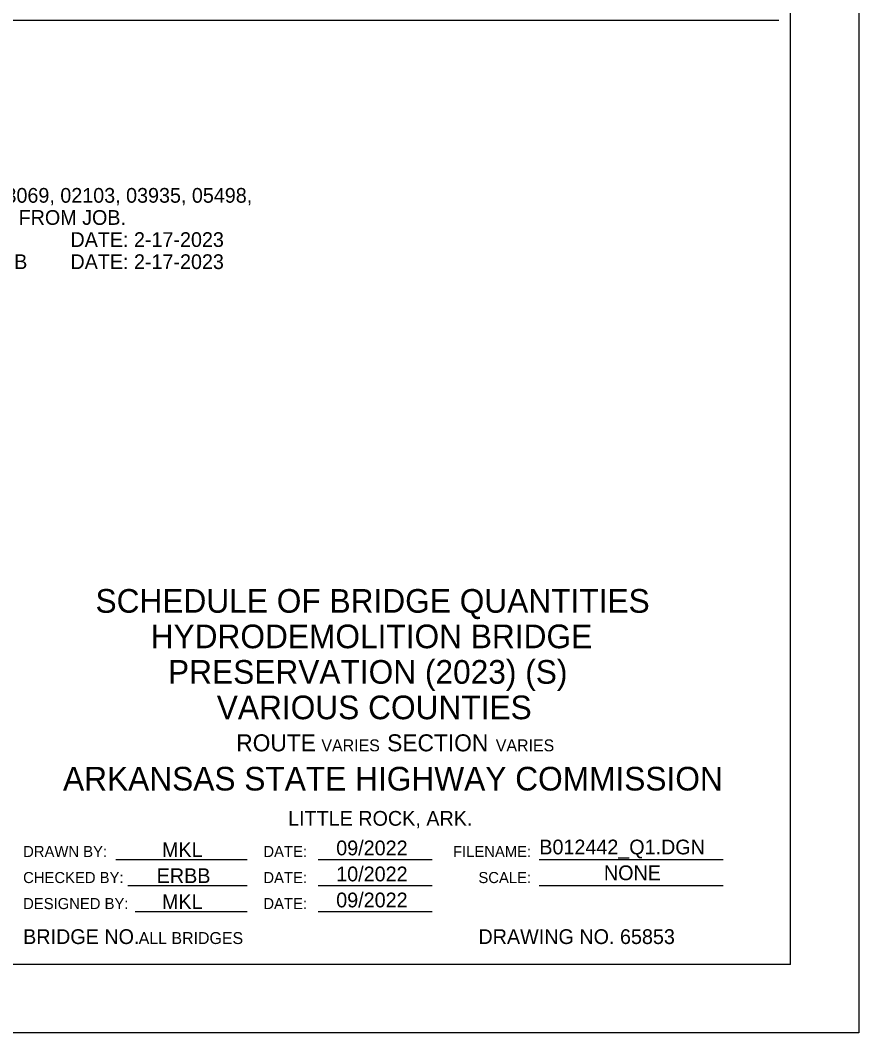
# Model space of a CAD drawing. Extents: x 18 to 14744716, y -5 to 1829144.
# Drawn here: x 44.68 to 51.78, y -5.37 to 3.2 of the extents above; entities that cross this region are included whole.
import ezdxf

# ---------------------------------------------------------------- set-up
doc = ezdxf.new("R2010")
doc.units = 0
for name, color, linetype in [('B_Copy In', 7, 'Continuous'), ('B_Text', 7, 'Continuous'), ('R_Border', 7, 'Continuous'), ('R_No Plot', 7, 'Continuous')]:
    doc.layers.add(name, color=color, linetype=linetype)

msp = doc.modelspace()

# ---------------------------------------------------------------- linework, layer by layer
at = {"layer": 'B_Text'}
for p, q in [((19.3916, 3.2008), (51.1014, 3.2008)), ((45.4897, -3.9052), (46.6013, -3.9052)), ((47.2016, -3.9052), (48.1658, -3.9052)), ((49.0717, -3.9042), (50.6292, -3.9042)), ((45.5911, -4.1255), (46.6013, -4.1255)), ((47.2016, -4.1255), (48.1658, -4.1255)), ((49.0717, -4.1245), (50.6292, -4.1245)), ((45.6521, -4.3459), (46.6013, -4.3459)), ((47.2016, -4.3459), (48.1658, -4.3459))]:
    msp.add_line(p, q, dxfattribs=at)
at = {"layer": 'R_Border'}
for q in [(51.2001, 16.0508), (19.2929, -4.7956)]:
    msp.add_line((51.2001, -4.7956), q, dxfattribs=at)
at = {"layer": 'R_No Plot'}
msp.add_lwpolyline([(17.7769, 16.6276), (51.7769, 16.6276), (51.7769, -5.3724), (17.7769, -5.3724)], close=True, dxfattribs=at)

# ---------------------------------------------------------------- texts
at = {"layer": 'B_Copy In'}
for s, height, p in [('SCHEDULE OF BRIDGE QUANTITIES', 0.2004, (45.3175, -1.8159)), ('HYDRODEMOLITION BRIDGE', 0.2004, (45.7841, -2.1165)), ('PRESERVATION (2023) (S)', 0.2004, (45.9312, -2.4171)), ('VARIOUS COUNTIES', 0.2004, (46.3438, -2.7177)), ('ROUTE    ', 0.144, (46.5087, -2.9895)), ('VARIES', 0.1008, (47.2293, -2.9895)), ('SECTION   ', 0.144, (47.7858, -2.9895)), ('VARIES', 0.1008, (48.7052, -2.9895)), ('MKL', 0.125, (45.8799, -3.8847)), ('09/2022', 0.125, (47.3545, -3.87)), ('B012442_Q1.DGN', 0.1248, (49.0738, -3.862)), ('ERBB', 0.125, (45.8352, -4.1051)), ('10/2022', 0.125, (47.3545, -4.0904)), ('NONE', 0.125, (49.6201, -4.0807)), ('MKL', 0.125, (45.8799, -4.3254)), ('09/2022', 0.125, (47.3545, -4.3107)), ('BRIDGE NO.      ', 0.125, (44.7048, -4.6211)), ('ALL BRIDGES', 0.1008, (45.6828, -4.6211)), ('DRAWING NO. 65853', 0.125, (48.5581, -4.6211))]:
    msp.add_text(s, height=height, dxfattribs=at).set_placement(p)
at = {"layer": 'B_Text'}
for s, height, p in [('BRIDGES 03070, 03069, 02103, 03935, 05498, ', 0.1248, (43.1084, 1.6557)), ('& 05497 REMOVED FROM JOB.', 0.1248, (43.1084, 1.4685)), ('DATE: 2-17-2023', 0.1248, (45.1052, 1.2813)), ('CHECKED BY: ERBB', 0.1248, (43.1084, 1.0941)), ('DATE: 2-17-2023', 0.1248, (45.1052, 1.0941)), ('ARKANSAS STATE HIGHWAY COMMISSION', 0.2004, (45.0427, -3.3213)), ('LITTLE ROCK, ARK.', 0.125, (46.947, -3.6195)), ('DRAWN BY:', 0.09375, (44.7048, -3.8847)), ('DATE:', 0.09375, (46.738, -3.8847)), ('FILENAME:', 0.09375, (48.3427, -3.8847)), ('CHECKED BY:', 0.09375, (44.7048, -4.1051)), ('DATE:', 0.09375, (46.738, -4.1051)), ('SCALE:', 0.09375, (48.5581, -4.1051)), ('DESIGNED BY:', 0.09375, (44.7048, -4.3254)), ('DATE:', 0.09375, (46.738, -4.3254))]:
    msp.add_text(s, height=height, dxfattribs=at).set_placement(p)

doc.saveas('drawing.dxf')
